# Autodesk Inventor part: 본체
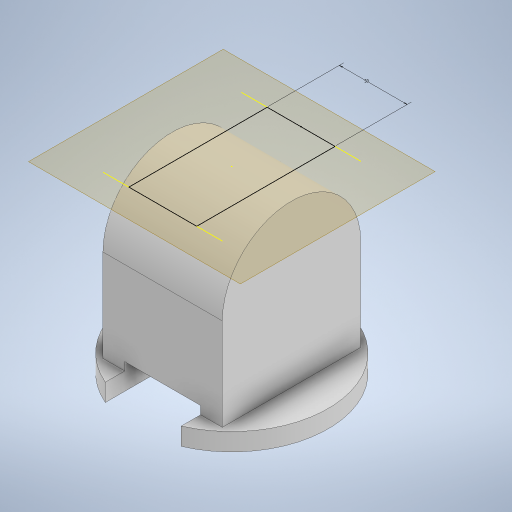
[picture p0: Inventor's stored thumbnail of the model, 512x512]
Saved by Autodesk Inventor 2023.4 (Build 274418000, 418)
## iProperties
Created: 2024-08
Part Number: 본체
Material: 일반
Document SubType Name: Modeling
Designer: user
Density: 1 g/cm^3
Appearance: 기본값
Author: user
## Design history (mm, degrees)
sketch "스케치1"
  geometry: L1 (0, 51)-(-81, 51); L2 (-81, 51)-(-81, -51); L3 (-81, -51)-(0, -51); A1 r 51 centre (0, 0) between (0, 51) and (0, -51); 1 further point
  constraints: 6 end point, 2 point on circle, 2 tangent, 1 centre point, 1 coincident, 1 horizontal, 1 parallel, 1 perpendicular
  dimensions: "d0" = 102 diameter of A1; "d1" = 81 distance of L1.start L1.end
extrude "돌출1" new body sketch "스케치1" stored distance "d2" = 88; taper "d3" = 0 deg
node "작업 평면1"
sketch "스케치2"
  geometry: C1 r 71 at (0, 0); 1 further point
  constraints: 1 centre point, 1 coincident
  dimensions: "d5" = 142 diameter of C1
extrude "돌출2" join sketch "스케치2" distance "d6" = 13; taper "d7" = 0 deg
sketch "스케치3"
  geometry: L1 (71, -68)-(-71, -68) reference; L2 (71, -81)-(-71, -81) reference; L3 (44, -68)-(-44, -68) reference; L4 (-44, 0)-(-44, -68) reference; L5 (-44, 0)-(44, 0) reference; L6 (44, -68)-(44, 0) reference; L7 (71, -81)-(-71, -81) reference; L8 (-28, -81)-(28, -81); L9 (28, -81)-(28, -62); L10 (28, -62)-(-28, -62); L11 (-28, -62)-(-28, -81); 5 further points
  constraints: 8 end point, 2 midpoint, 2 parallel, 1 horizontal, 1 perpendicular, 1 point on line, 1 vertical alignment
  dimensions: "d8" = 56 distance of L9.end L10.end; "d9" = 19 distance of L8.end L9.end
extrude "돌출3" cut sketch "스케치3" extent not by distance; stored distance "d10" = 0; taper "d11" = 0 deg
node "작업 평면2"
sketch "스케치4"
  geometry: L1 (44, -51)-(-44, -51) reference; L2 (-44, 51)-(44, 51) reference; L3 (25, -51)-(-25, -51); L4 (-25, -51)-(-25, 51); L5 (-25, 51)-(25, 51); L6 (25, 51)-(25, -51); 2 further points
  constraints: 8 end point, 2 parallel, 2 point on line, 1 horizontal, 1 midpoint, 1 perpendicular, 1 vertical alignment
  dimensions: "d12" = 50 distance between parallel lines of L4 L6
node "솔리드1"
node "투영된 루프1"
node "투영된 루프2"
other parameters: "d4" = -81
